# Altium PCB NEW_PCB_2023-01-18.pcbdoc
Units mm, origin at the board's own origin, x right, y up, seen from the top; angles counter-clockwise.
Board outline 132.01 x 95.65 mm, 2 copper layers (Top Layer, Bottom Layer); 25 components, 69 nets, 157 pads, 22 vias.
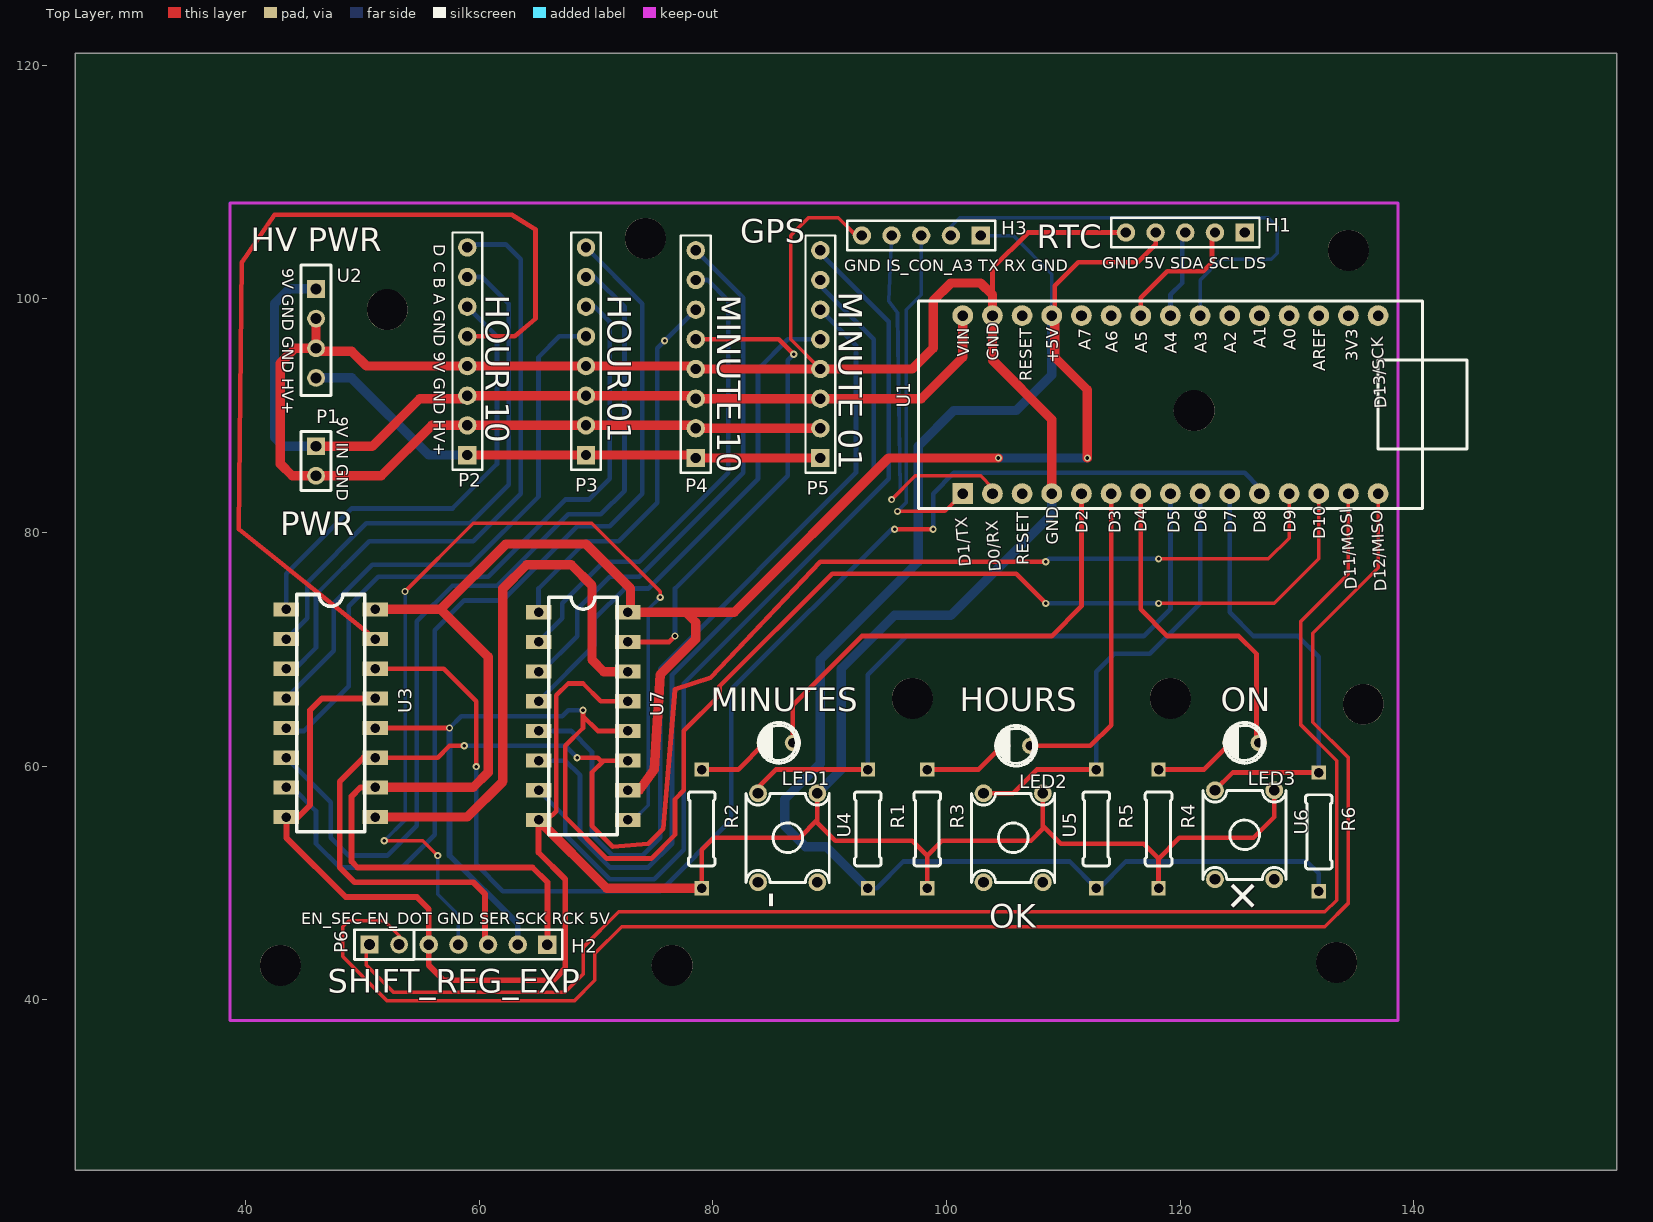
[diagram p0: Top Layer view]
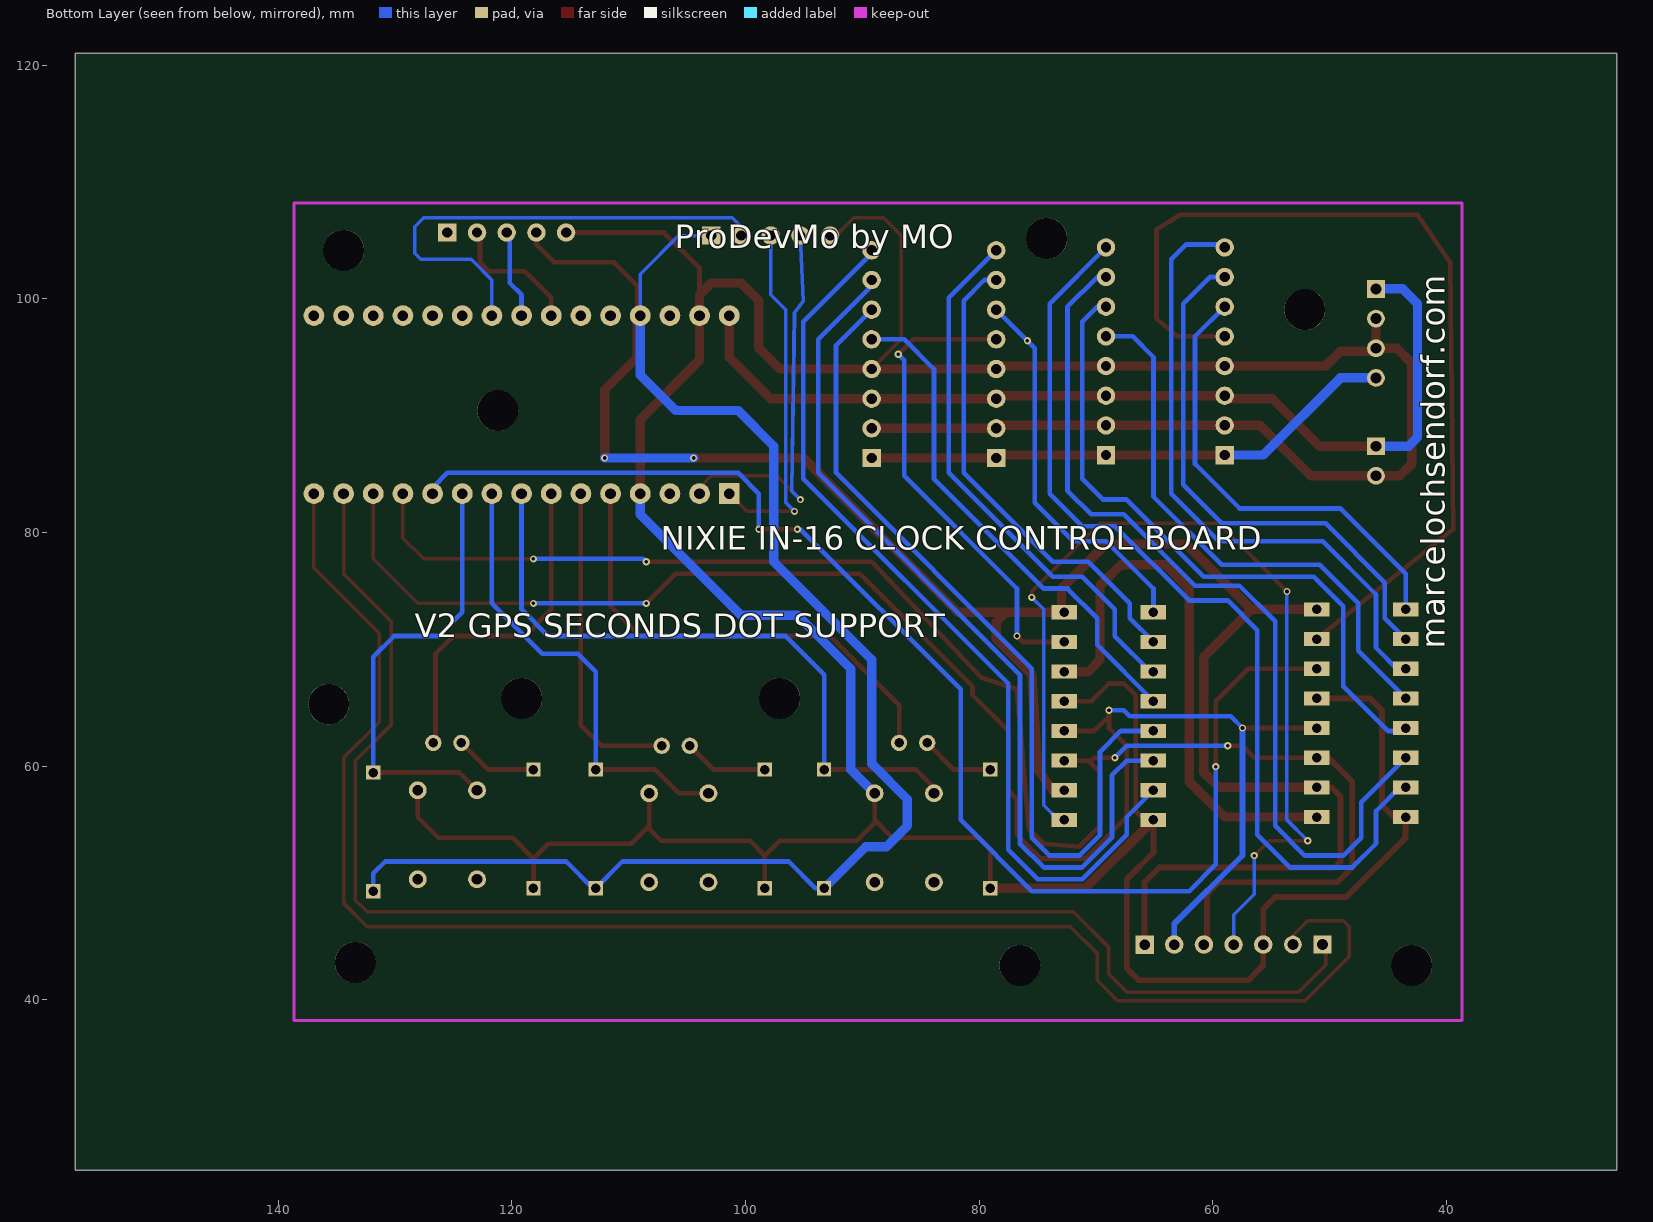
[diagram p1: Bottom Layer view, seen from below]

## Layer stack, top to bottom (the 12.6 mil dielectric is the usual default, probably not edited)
Top Layer: signal copper (thickness not stored)
Dielectric: dielectric 0.32, FR-4, Dk 4.8
Bottom Layer: signal copper (thickness not stored)

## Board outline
157.408,25.4 25.4,25.4 25.4,121.054 157.408,121.054

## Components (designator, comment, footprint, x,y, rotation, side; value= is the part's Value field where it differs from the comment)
H1 "Header-Female-2.54_1x5" HDR-5X1/2.54 120.451,105.687 r180 top
H2 "Header-Female-2.54_1x5" HDR-5X1/2.54 60.761,44.727 r180 top
H3 "Header-Female-2.54_1x5" HDR-5X1/2.54 97.845,105.433 r180 top
LED1 "LEDOrange orange 3AO4UD" LED-3MM 85.653,61.999 r180 top
LED2 "LEDOrange orange 3AO4UD" LED-3MM 105.973,61.745 r180 top
LED3 "LEDOrange orange 3AO4UD" LED-3MM 125.531,61.999 r180 top
P1 "1*2_Header" "1*2 HEADER" 46.029,87.399 r0 top
P2 "Header2.54mm 1*8P" HDR-8X1/2.54 58.983,94.257 r90 top
P3 "Header2.54mm 1*8P" HDR-8X1/2.54 69.143,94.257 r90 top
P4 "Header2.54mm 1*8P" HDR-8X1/2.54 78.541,94.003 r90 top
P5 "Header2.54mm 1*8P" HDR-8X1/2.54 89.209,94.003 r90 top
P6 "1*2_Header" "1*2 HEADER" 50.601,44.727 r90 top
R1 "RESISTOR" RTH025W 93.273,54.633 r270 top
R2 "RESISTOR" RTH025W 79.049,54.633 r270 top
R3 "RESISTOR" RTH025W 98.353,54.633 r270 top
R4 "RESISTOR" RTH025W 118.165,54.633 r270 top
R5 "RESISTOR" RTH025W 112.831,54.633 r270 top
R6 "RESISTOR" RTH025W 131.881,54.379 r270 top
U1 "ARDUINO_NANO" ARDUINO_NANO 119.181,90.955 r90 top
U2 "Header 1*4P" HEADER1*4P 43.489,98.321 r0 top
U3 "74HC595" DIL16 47.299,64.539 r270 top
U4 "PUSH_BUTTON" PUSH_BUTTON 88.955,57.681 r270 top
U5 "PUSH_BUTTON" PUSH_BUTTON 108.259,57.681 r270 top
U6 "PUSH_BUTTON" PUSH_BUTTON 128.071,57.935 r270 top
U7 "74HC595" DIL16 68.889,64.285 r270 top

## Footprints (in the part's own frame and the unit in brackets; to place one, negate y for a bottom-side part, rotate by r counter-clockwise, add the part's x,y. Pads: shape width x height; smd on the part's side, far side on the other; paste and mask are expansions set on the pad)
"1*2 HEADER" [mil]
  rect 60x60 hole 36: 1(0,0)
  round 60 hole 36: 2(0,-100)
  silkscreen extent -50,-150 50,50
ARDUINO_NANO [mil]
  rect 70x70 hole 36: 1(-300,700)
  round 70 hole 36: 2(-300,600) 3(-300,500) 4(-300,400) 5(-300,300) 6(-300,200) 7(-300,100) 8(-300,0) 9(-300,-100) 10(-300,-200) 11(-300,-300) 12(-300,-400) 13(-300,-500) 14(-300,-600) 15(-300,-700) 16(300,-700) 17(300,-600) 18(300,-500) 19(300,-400) 20(300,-300) 21(300,-200) 22(300,-100) 23(300,0) 24(300,100) 25(300,200) 26(300,300) 27(300,400) 28(300,500) 29(300,600) 30(300,700)
  silkscreen extent -350,-1000 350,850
DIL16 [mil]
  rect 47.7x85.9 hole 32: 1(-349.95,-149.95) 2(-249.95,-149.95) 3(-149.95,-149.95) 4(-49.95,-149.95) 5(50.05,-149.95) 6(150.05,-149.95) 7(250.05,-149.95) 8(350.05,-149.95) 9(350.05,150.05) 10(250.05,150.05) 11(150.05,150.05) 12(50.05,150.05) 13(-49.95,150.05) 14(-149.95,150.05) 15(-249.95,150.05) 16(-349.95,150.05)
  silkscreen extent -400,-115 400,115
HDR-5X1/2.54 [mil]
  rect 62x62 hole 35: 1(-200,0)
  round 62 hole 35: 2(-100,0) 3(0,0) 4(100,0) 5(200,0)
  silkscreen extent -250,-50 250,50
HDR-8X1/2.54 [mil]
  rect 62x62 hole 35: 1(-300,0)
  round 62 hole 35: 2(-200,0) 3(-100,0) 4(0,0) 5(100,0) 6(200,0) 7(300,0) 8(400,0)
  silkscreen extent -350,-50 450,50
HEADER1*4P [mil]
  rect 60x60 hole 36: 1(100,100)
  round 60 hole 36: 2(100,0) 3(100,-100) 4(100,-200)
  silkscreen extent 50,-260 150,180
LED-3MM [mm]
  round 1.4 hole 0.8: 1(-1.204,0.003) 2(1.199,0.003)
  silkscreen extent -1.75,-1.75 1.75,1.75
PUSH_BUTTON [mil]
  round 60 hole 36: 1(0,0) 2(0,-200) 3(300,-200) 4(300,0)
  silkscreen extent 0,-240 300,40
RTH025W [mil]
  rect 47.7x47.7 hole 32: 1(-199.95,0.05) 2(200.05,0.05)
  silkscreen extent -125,-45 125,45

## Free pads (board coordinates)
  round 3.5 hole 3.5 unplated: ""(42.981,42.949) ""(52.125,99.083) ""(74.223,105.179) ""(76.509,42.949) ""(97.083,65.809) ""(119.181,65.809) ""(121.213,90.447) ""(133.405,43.203) ""(134.421,104.163) ""(135.691,65.301)

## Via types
v1: diameter 0.62, hole 0.305, Top Layer to Bottom Layer, tented both sides, 22 vias

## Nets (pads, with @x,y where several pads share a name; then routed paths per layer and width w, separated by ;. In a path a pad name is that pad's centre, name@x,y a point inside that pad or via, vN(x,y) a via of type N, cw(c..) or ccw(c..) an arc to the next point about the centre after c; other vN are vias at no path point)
+5V: H1.4 H2.1 H3.1 R1.2 R5.2 R6.2 U1.27 U3.10 U3.16 U7.10 U7.16 | length 294.9
  Top Layer w0.4: U1.27 109.275,98.829 109.275,101.115 111.307,103.147 116.387,103.147 117.911,104.671 H1.4
  Top Layer w0.5: U3.10@51.109,58.189 49.839,58.189 49.077,57.427 49.077,51.839 49.585,51.331 64.571,51.331 65.841,50.061 H2.1
  Top Layer w0.8: U3.10@51.109,58.189 59.491,58.189 60.761,59.459 60.761,69.365 56.697,73.429 ; U3.16@51.109,73.429 56.697,73.429 ; U7.10@72.699,57.935 73.715,57.935 74.985,59.713 75.493,67.841 78.541,70.889 78.541,72.319 77.685,73.175 ; v1(104.449,86.383) 95.051,86.383 81.843,73.175 72.699,73.175 72.953,73.429 72.953,75.207 69.143,79.017 62.285,79.017 56.697,73.429 ; U1.27 109.275,98.321 109.275,95.019 112.069,92.225 v1(112.069,86.383)
  Bottom Layer w0.3: H3.1 105.719,105.433 109.021,102.131 U1.27
  Bottom Layer w0.4: R1.2@93.273,49.553 94.035,49.553 96.321,51.839 110.545,51.839 112.831,49.553 113.085,49.553 115.371,51.839 130.865,51.839 131.881,50.823 R6.2@131.881,49.299
  Bottom Layer w0.8: R1.2@93.273,49.553 89.717,53.109 87.939,53.109 86.161,54.887 86.161,57.173 89.209,60.221 89.209,69.111 97.591,77.493 97.591,87.399 100.639,90.447 105.973,90.447 109.021,93.495 U1.27 ; v1(104.449,86.383) v1(112.069,86.383)
GND: H1.5 H2.5 H3.5 P1.2 P2.2 P2.4 P3.2 P3.4 P4.2 P4.4 P5.2 P5.4 R2.2 R3.2 R4.2 U1.4 U1.29 U2.2 U2.3 U3.8 U3.13 U4.1 U5.1 U6.1 U7.8 U7.13 | length 399
  Top Layer w0.3: P5.4 86.669,96.543 86.669,105.433 88.193,106.957 90.733,106.957 92.257,105.433 H3.5
  Top Layer w0.4: U7.8@65.079,55.395 65.841,55.395 66.603,56.157 66.603,66.063 67.619,67.079 68.889,67.079 70.413,65.555 U7.13@72.699,65.555 ; R2.2@79.049,49.553 79.049,52.855 80.065,53.871 87.431,53.871 88.955,55.395 U4.1 88.955,55.141 90.479,53.617 97.083,53.617 98.353,52.347 ; U1.29 103.941,102.639 106.989,105.687 H1.5 ; R4.2@118.165,49.553 118.165,52.093 ; U6.1 128.071,55.649 126.293,53.871 119.943,53.871 118.165,52.093 ; 98.353,52.347 98.353,49.553 98.353,52.347 ; 98.353,52.347 99.623,53.617 107.243,53.617 108.259,54.633 U5.1 108.259,54.887 109.783,53.363 116.895,53.363 118.165,52.093
  Top Layer w0.5: U3.13@51.109,65.809 46.537,65.809 45.521,64.793 45.521,56.665 44.505,55.649 43.489,55.649 43.489,53.871 48.569,48.791 54.665,48.791 55.681,47.775 H2.5 55.681,42.949 56.951,41.679 66.349,41.679 67.365,42.695 67.365,50.315 65.079,52.601 U7.8@65.079,55.395
  Top Layer w0.8: U2.2 U2.3 ; U7.8@65.079,55.395 70.921,49.553 R2.2@79.049,49.553 ; P5.2 P4.2 78.287,89.177 P3.2 P2.2 55.935,89.177 51.617,84.859 P1.2 43.997,84.859 42.981,85.875 42.981,94.511 44.251,95.781 U2.3 ; U1.4 109.021,89.685 103.941,94.765 U1.29 103.941,100.353 102.925,101.369 100.385,101.369 98.861,99.845 98.861,95.781 97.083,94.003 P5.4 P4.4 78.287,94.257 P3.4 P2.4 50.347,94.257 49.077,95.527 46.283,95.527 U2.3
  Bottom Layer w0.8: U4.1 90.987,59.713 90.987,68.349 95.559,72.921 100.385,72.921 109.021,81.557 U1.4
H1_1: H1.1
LED1_2: LED1.2 R2.1 | length 6.4
  Top Layer w0.4: R2.1@79.049,59.713 82.171,59.713 LED1.2
LED2_2: LED2.2 R3.1 | length 7.3
  Top Layer w0.4: R3.1@98.353,59.713 102.745,59.713 LED2.2
LED3_2: LED3.2 R4.1 | length 7.1
  Top Layer w0.4: R4.1@118.165,59.713 122.049,59.713 LED3.2
P2_5: P2.5 U3.15 | length 79.5
  Top Layer w0.4: U3.15@51.109,70.889 39.425,80.287 39.679,103.147 42.473,107.211 62.793,107.211 64.825,105.941 64.825,98.321 63.047,96.797 P2.5
P2_6: P2.6 U3.1 | length 39.5
  Bottom Layer w0.4: U3.1@43.489,73.429 43.489,76.477 49.077,82.065 57.713,82.065 61.523,85.875 61.523,96.797 P2.6
P2_7: P2.7 U3.2 | length 46.3
  Bottom Layer w0.4: U3.2@43.489,70.889 45.267,72.667 45.267,75.715 50.347,80.795 59.237,80.795 62.539,84.097 62.539,99.591 60.253,101.877 P2.7
P2_8: P2.8 U3.3 | length 54.2
  Bottom Layer w0.4: U3.3@43.489,68.349 44.251,68.349 46.029,70.127 46.029,74.699 50.601,79.271 59.491,79.271 63.555,83.335 63.555,103.401 62.285,104.671 59.237,104.671 P2.8
P3_5: P3.5 U3.4 | length 47.9
  Bottom Layer w0.4: U3.4@43.489,65.809 47.553,69.873 47.553,73.937 50.855,77.239 59.237,77.239 65.079,83.081 65.079,95.019 66.857,96.797 P3.5
P3_6: P3.6 U3.5 | length 56.8
  Bottom Layer w0.4: U3.5@43.489,63.269 43.743,63.015 45.013,63.015 48.823,66.825 48.823,73.683 51.363,76.223 60.761,76.223 67.365,82.827 69.397,82.827 71.175,84.605 71.175,98.067 69.905,99.337 P3.6
P3_7: P3.7 U3.6 | length 77.5
  Bottom Layer w0.4: U3.6@43.489,60.729 47.299,56.919 47.299,53.871 48.823,52.347 52.125,52.347 54.665,54.887 54.665,72.413 57.713,75.461 61.523,75.461 67.619,81.557 70.413,81.557 72.445,83.589 72.445,99.337 69.905,101.877 P3.7
P3_8: P3.8 U3.7 | length 81.6
  Bottom Layer w0.4: U3.7@43.489,58.189 43.997,58.189 46.029,56.157 46.029,53.363 48.061,51.331 53.395,51.331 56.189,54.125 56.189,71.651 58.729,74.191 62.031,74.191 68.381,80.541 71.175,80.541 73.969,83.335 73.969,99.591 P3.8
P4_5: P4.5 U7.15 | length 41.5
  Top Layer w0.4: U7.15@72.699,70.635 76.255,70.635 v1(76.763,71.143) ; P4.5 85.653,96.543 v1(86.923,95.273)
  Bottom Layer w0.4: v1(76.763,71.143) 76.763,75.207 86.415,84.859 86.415,94.765 v1(86.923,95.273)
P4_6: P4.6 U7.1 | length 33.1
  Bottom Layer w0.4: U7.1@65.079,73.175 65.079,75.207 69.143,79.271 71.937,79.271 75.239,82.573 75.239,95.781 v1(75.874,96.416) P4.6
P4_7: P4.7 U7.2 | length 41.3
  Bottom Layer w0.4: U7.2@65.079,70.635 67.111,72.667 67.111,73.937 70.667,77.493 73.715,77.493 81.335,85.113 81.335,99.845 79.557,101.623 P4.7
P4_8: P4.8 U7.3 | length 46.6
  Bottom Layer w0.4: U7.3@65.079,68.095 65.333,68.095 68.381,71.143 68.381,73.429 71.175,76.223 73.715,76.223 82.605,85.113 82.605,100.099 P4.8
P5_5: P5.5 U7.4 | length 43.8
  Bottom Layer w0.4: U7.4@65.079,65.555 69.905,70.381 69.905,72.667 72.445,75.207 74.477,75.207 83.875,84.605 83.875,94.003 86.415,96.543 P5.5
P5_6: P5.6 U7.5 | length 73
  Bottom Layer w0.4: U7.5@65.079,63.015 67.873,63.015 69.651,61.237 69.651,54.125 71.429,52.347 73.969,52.347 75.493,53.871 75.493,68.349 92.257,85.113 92.257,96.035 P5.6
P5_7: P5.7 U7.6 | length 76.5
  Bottom Layer w0.4: U7.6@65.079,60.475 67.365,60.475 68.635,59.205 68.635,53.871 71.175,51.331 74.477,51.331 76.509,53.363 76.509,67.841 93.781,85.113 93.781,96.543 89.209,101.115 P5.7
P5_8: P5.8 U7.7 | length 78.5
  Bottom Layer w0.4: U7.7@65.079,57.935 67.365,55.649 67.365,54.125 71.175,50.315 74.985,50.315 77.525,52.855 77.525,67.079 95.051,84.605 95.051,98.067 89.209,103.909 P5.8
S$17: 
S$18: 
S$22: 
S$26: 
S$38: 
S$41: 
S$44: 
S$55: 
S$59: 
S$63: 
S$1261: 
  other v1: 108.513,73.937
U1_1: H3.3 U1.1 | length 30.7
  Top Layer w0.3: v1(95.813,81.811) 99.877,81.811 U1.1
  Bottom Layer w0.3: v1(95.813,81.811) 96.575,82.573 96.575,99.083 97.845,100.353 H3.3
U1_2: H3.4 U1.2 | length 33.6
  Top Layer w0.3: v1(95.305,82.827) 97.337,84.859 102.925,84.859 103.941,83.843 U1.2
  Bottom Layer w0.3: v1(95.305,82.827) 96.067,83.589 95.813,98.829 95.051,99.845 H3.4
U1_3: U1.3
U1_5: LED1.1 U1.5 | length 41.1
  Top Layer w0.4: LED1.1 86.857,65.235 92.765,71.143 109.021,71.143 111.561,73.683 U1.5
U1_6: LED2.1 U1.6 | length 27.5
  Top Layer w0.4: LED2.1 112.321,61.742 114.101,63.523 U1.6
U1_7: LED3.1 U1.7 | length 29.1
  Top Layer w0.4: U1.7 116.641,73.429 118.927,71.143 125.023,71.143 126.547,69.619 126.547,62.184 LED3.1
U1_8: R1.1 U1.8 U4.2 | length 56.8
  Top Layer w0.4: U4.2 83.875,58.189 85.399,59.713 R1.1@93.273,59.713
  Bottom Layer w0.4: R1.1@93.273,59.713 93.273,67.841 96.575,71.143 116.895,71.143 119.181,73.429 U1.8
U1_9: R5.1 U1.9 U5.2 | length 39.6
  Top Layer w0.4: U5.2 105.719,57.681 107.751,59.713 R5.1@112.831,59.713
  Bottom Layer w0.4: R5.1@112.831,59.713 112.831,68.095 114.355,69.619 117.403,69.619 121.721,73.937 U1.9
U1_10: R6.1 U1.10 U6.2 | length 38.8
  Top Layer w0.4: U6.2 124.515,59.459 R6.1@131.881,59.459
  Bottom Layer w0.4: U1.10 124.261,73.175 126.293,71.143 130.103,71.143 131.881,69.365 R6.1@131.881,59.459
U1_11: U1.11 U3.14 | length 115.7
  Top Layer w0.4: U3.14@51.109,68.349 56.951,68.349 59.745,65.555 v1(59.745,59.967) ; v1(95.559,80.287) v1(98.861,80.287)
  Bottom Layer w0.4: v1(59.745,59.967) 59.745,51.585 62.031,49.299 75.493,49.299 81.589,55.395 81.589,66.571 v1@95.305,80.287 ; v1(98.861,80.287) 98.861,83.335 100.639,85.113 125.531,85.113 126.801,83.843 U1.11
U1_12: H2.3 U1.12 U3.11 U7.11 | length 140.7
  Top Layer w0.3: v1(118.165,77.747) 127.563,77.747 129.341,79.525 U1.12
  Top Layer w0.4: U3.11@51.109,60.729 56.443,60.729 57.459,61.745 v1(58.729,61.745) ; v1(68.381,60.729) 70.159,60.729 70.413,60.475 72.699,60.475 70.667,60.475 69.651,59.459 69.651,54.887 71.429,53.109 74.477,53.363 75.747,54.633 76.763,66.571 79.811,67.587 89.209,77.493 95.305,77.493 v1(108.513,77.493)
  Top Layer w0.5: U3.11@51.109,60.729 50.093,60.729 48.061,58.697 48.061,51.331 49.331,50.061 59.491,50.061 60.507,49.045 60.507,44.981 H2.3
  Bottom Layer w0.4: v1(58.729,61.745) 67.365,61.745 v1(68.381,60.729) ; v1(108.513,77.493) 108.767,77.747 v1(118.165,77.747)
U1_13: H2.2 U1.13 U3.12 U7.12 | length 143.5
  Top Layer w0.3: v1(118.165,73.937) 128.071,73.937 131.881,77.747 U1.13
  Top Layer w0.4: U3.12@51.109,63.269 v1(57.459,63.269) ; U7.12@72.699,63.015 70.159,63.015 68.889,64.285 v1(68.889,64.793) 68.889,63.269 67.365,61.745 67.365,55.649 70.921,52.093 74.731,52.093 76.763,54.125 76.763,57.173 77.525,57.935 77.525,63.015 80.573,66.063 80.573,66.825 90.225,76.477 105.973,76.477 108.513,73.937
  Bottom Layer w0.4: v1(57.459,63.269) 58.475,64.285 67.111,64.285 67.619,64.793 v1(68.889,64.793) ; 108.513,73.937 v1(118.165,73.937)
  Bottom Layer w0.5: v1(57.459,63.269) 57.459,52.347 63.301,46.505 H2.2
U1_14: P6.1 U1.14 | length 128.2
  Top Layer w0.3: P6.1 50.347,44.473 50.347,42.949 52.633,40.663 67.365,40.663 68.889,42.187 68.889,44.473 71.937,47.521 132.389,47.521 133.405,48.537 133.405,60.475 130.357,63.523 130.357,72.413 134.421,76.477 U1.14
U1_15: P6.2 U1.15 | length 140
  Top Layer w0.3: P6.2 53.141,45.489 51.871,46.759 48.823,46.759 48.315,46.251 48.315,43.711 52.125,39.901 68.127,39.901 69.905,41.679 69.905,43.965 72.191,46.251 132.389,46.251 134.421,48.283 134.421,60.729 131.373,63.777 131.373,71.397 136.961,76.985 U1.15
U1_16: U1.16
U1_17: U1.17
U1_18: U1.18
U1_19: U1.19
U1_20: U1.20
U1_21: U1.21
U1_22: H3.2 U1.22 | length 42.2
  Bottom Layer w0.3: H3.2 100.385,106.195 101.147,106.957 127.563,106.957 128.325,106.195 128.325,103.909 127.817,103.401 123.499,103.401 121.721,101.623 U1.22
U1_23: H1.3 U1.23 | length 7.6
  Bottom Layer w0.4: U1.23 119.181,100.353 120.197,101.369 120.197,105.433 H1.3
U1_24: H1.2 U1.24 | length 11.5
  Top Layer w0.4: U1.24 116.641,100.099 118.927,102.385 121.975,102.385 122.737,103.147 122.737,105.433 H1.2
U1_25: U1.25
U1_26: U1.26
U1_28: U1.28
U2_4: P2.1 P3.1 P4.1 P5.1 U2.4 | length 46
  Top Layer w0.8: P2.1 P3.1 78.287,86.637 P4.1 P5.1
  Bottom Layer w0.8: U2.4 49.077,93.241 55.681,86.637 P2.1
U3_9: U3.9 U7.14 | length 47.7
  Top Layer w0.8: U3.9@51.109,55.649 58.983,55.649 62.031,58.697 62.031,75.207 64.063,77.239 67.873,77.239 69.651,75.461 69.651,69.111 70.667,68.095 U7.14@72.699,68.095
U4_3: U4.3
U4_4: U4.4
U5_3: U5.3
U5_4: U5.4
U6_3: U6.3
U6_4: U6.4
U7_9: H2.4 U7.9 | length 83.2
  Top Layer w0.3: v1(51.871,53.617) 55.173,53.617 v1(56.443,52.347) ; v1(53.649,74.953) 59.491,80.795 69.651,80.795 75.493,74.953 v1(75.493,74.445)
  Bottom Layer w0.3: v1(51.871,53.617) 53.649,55.395 v1(53.649,74.953) ; v1(56.443,52.347) 56.443,49.045 58.221,47.267 H2.4 ; U7.9@72.699,55.395 73.207,55.395 74.477,56.665 74.477,73.429 v1(75.493,74.445)
VCC: P1.1 P2.3 P3.3 P4.3 P5.3 U1.30 U2.1 | length 81.7
  Top Layer w0.8: P1.1 50.855,87.399 54.919,91.463 58.729,91.463 P2.3 P3.3 78.287,91.717 P4.3 P5.3 97.845,91.463 101.401,95.019 U1.30
  Bottom Layer w0.8: P1.1 43.235,87.399 42.473,88.161 42.473,99.591 43.743,100.861 U2.1

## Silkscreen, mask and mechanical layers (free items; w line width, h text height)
Top Overlay:
  text "GPS" at 82.351,104.833 h2.03
  text "D C B A GND 9V GND HV+" at 56.098,104.671 h1 r270
  text "RTC" at 107.751,104.325 h2.03
  text "HV PWR" at 40.441,104.071 h2.03
  text "9V GND GND HV+" at 43.144,102.639 h1 r270
  text "GND 5V SDA SCL DS" at 113.339,102.609 h1
  text "GND IS_CON_A3 TX RX GND" at 91.241,102.355 h1
  text "MINUTE 01" at 90.802,100.607 h2.03 r270
  text "HOUR 10" at 60.576,100.353 h2.03 r270
  text "HOUR 01" at 70.99,100.353 h2.03 r270
  text "MINUTE 10" at 80.388,100.353 h2.03 r270
  text "9V IN GND" at 47.815,89.901 h1 r270
  text "PWR" at 42.981,79.779 h2.03
  text "MINUTES" at 79.811,64.701 h2.03
  text "HOURS" at 101.147,64.701 h2.03
  text "ON" at 123.499,64.701 h2.03
  text "-" at 86.137,47.775 h3 r90
  text "+" at 125.068,46.757 h3 r45
  text "EN_SEC EN_DOT GND SER SCK RCK 5V" at 44.759,46.475 h1
  text "OK" at 103.687,46.159 h2.03
  text "SHIFT_REG_EXP" at 47.045,40.603 h2
Bottom Overlay:
  text "ProDevMo by MO" at 106.08,104.324 h2.03
  text "NIXIE IN-16 CLOCK CONTROL BOARD" at 107.243,78.509 h2.03
  text "V2 GPS SECONDS DOT SUPPORT" at 128.344,71.05 h2.03
  text "marcelochsendorf.com" at 40.132,70.034 h2.03 r270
